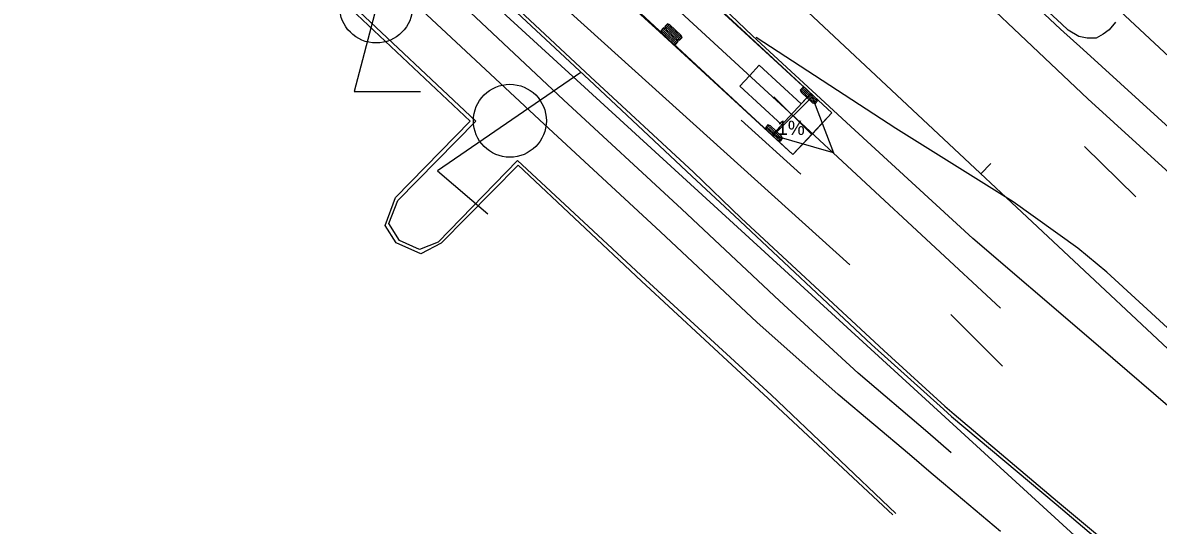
# Model space of a CAD drawing. Extents: x 1475900 to 1484331, y 375914 to 383395.
# Drawn here: x 1479629.9 to 1479789.2, y 379755.2 to 379825.7 of the extents above; entities that cross this region are included whole.
import ezdxf

# ---------------------------------------------------------------- set-up
doc = ezdxf.new("R2010")
doc.units = 0
for name, color, linetype in [('LT_X_Poles', 7, 'Continuous'), ('PM_X_CL_Double_Solid', 7, 'Continuous'), ('PM_X_Lane_Line', 7, 'Continuous'), ('PM_X_Misc', 7, 'Continuous'), ('PV_X_Curb', 7, 'Continuous'), ('PV_X_Walk', 7, 'Continuous'), ('RW_X_CL_20', 7, 'Continuous'), ('RW_X_Esmt_SH', 7, 'Continuous'), ('RW_X_Text', 7, 'Continuous')]:
    doc.layers.add(name, color=color, linetype=linetype)

# ---------------------------------------------------------------- blocks, each defined once
blk = doc.blocks.new('LPOLE')
at = {"layer": 'LT_X_Poles'}
blk.add_lwpolyline([(0.00999, 0.03751), (-0.01001, -0.0385), (0.02, -0.0385)], dxfattribs=at)
blk.add_circle((0, 0), 0.01651, dxfattribs=at)

msp = doc.modelspace()

# ---------------------------------------------------------------- linework, layer by layer
at = {"layer": 'PM_X_CL_Double_Solid'}
for points in [[(1479794.22, 379768.77), (1479779.09, 379781.77), (1479763.16, 379795.43), (1479746.62, 379810.62), (1479732.24, 379823.87), (1479714.72, 379840.65), (1479700.71, 379853.61), (1479677.93, 379875.07)], [(1479803.53, 379770.9), (1479781.95, 379790.71), (1479777.89, 379794.07), (1479768.81, 379800.57), (1479752.35, 379810.89), (1479732.76, 379823.63)]]:
    msp.add_lwpolyline(points, dxfattribs=at)
at = {"layer": 'PM_X_Lane_Line'}
for p, q in [((1479739.04, 379804.47), (1479730.66, 379812.05)), ((1479786.01, 379801.28), (1479778.82, 379808.36)), ((1479767.32, 379777.53), (1479760.1, 379784.77))]:
    msp.add_line(p, q, dxfattribs=at)
at = {"layer": 'PM_X_Misc'}
for p, q in [((1479735.27, 379810), (1479740.61, 379815.33)), ((1479740.61, 379810), (1479735.27, 379815.33)), ((1479767.04, 379785.65), (1479737.72, 379812.86))]:
    msp.add_line(p, q, dxfattribs=at)
for points in [[(1479725.98, 379829.12), (1479740.44, 379815.79), (1479735, 379809.93), (1479685.31, 379855.76)], [(1479724.38, 379830.7), (1479743.38, 379813.07), (1479737.93, 379807.21), (1479719.19, 379824.44), (1479707.65, 379835)], [(1479721.78, 379823.02), (1479719.72, 379824.93), (1479719.59, 379824.78), (1479721.64, 379822.88), (1479721.5, 379822.73), (1479719.45, 379824.63), (1479719.41, 379824.59), (1479719.57, 379824.25), (1479721.11, 379822.82), (1479721.46, 379822.68), (1479721.82, 379823.07), (1479721.66, 379823.41), (1479720.12, 379824.84), (1479719.77, 379824.98), (1479719.41, 379824.59)], [(1479722.32, 379823.61), (1479720.27, 379825.51), (1479720.13, 379825.37), (1479722.18, 379823.46), (1479722.05, 379823.32), (1479720, 379825.22), (1479719.95, 379825.17), (1479720.12, 379824.84), (1479721.66, 379823.41), (1479722, 379823.27), (1479722.37, 379823.66), (1479722.2, 379823.99), (1479720.66, 379825.42), (1479720.31, 379825.56), (1479719.95, 379825.17)], [(1479741.34, 379814.7), (1479739.28, 379816.6), (1479739.14, 379816.45), (1479741.2, 379814.55), (1479741.07, 379814.4), (1479739.01, 379816.3), (1479738.96, 379816.25), (1479739.13, 379815.92), (1479740.67, 379814.49), (1479741.02, 379814.36), (1479741.38, 379814.75), (1479741.21, 379815.08), (1479739.67, 379816.51), (1479739.32, 379816.64), (1479738.96, 379816.25)], [(1479736.44, 379809.42), (1479734.38, 379811.32), (1479734.24, 379811.17), (1479736.3, 379809.27), (1479736.17, 379809.13), (1479734.11, 379811.02), (1479734.06, 379810.98), (1479734.23, 379810.64), (1479735.77, 379809.22), (1479736.12, 379809.08), (1479736.48, 379809.47), (1479736.32, 379809.81), (1479734.77, 379811.23), (1479734.42, 379811.37), (1479734.06, 379810.98)]]:
    msp.add_lwpolyline(points, dxfattribs=at)
for points in [[(1479737.93, 379807.21), (1479715.94, 379827.62), (1479718.67, 379830.55), (1479721.39, 379833.48), (1479743.38, 379813.07), (1479740.65, 379810.14)], [(1479731.84, 379818.28), (1479733.2, 379819.75), (1479739.08, 379814.33), (1479740.43, 379815.8), (1479743.6, 379807.44), (1479735.01, 379809.92), (1479736.37, 379811.39), (1479730.48, 379816.81)]]:
    msp.add_lwpolyline(points, close=True, dxfattribs=at)
at = {"layer": 'PV_X_Curb'}
for points in [[(1479752.34, 379756.82), (1479734.89, 379773.49), (1479717.23, 379789.66), (1479699.3, 379806.4), (1479688.16, 379794.93), (1479685.53, 379793.9), (1479682.73, 379795.16), (1479681.26, 379797.55), (1479682.49, 379800.75), (1479693.46, 379811.91), (1479675.55, 379828.75), (1479655.83, 379847.06), (1479640.19, 379861.81), (1479628.56, 379849)], [(1479751.93, 379756.63), (1479734.45, 379772.98), (1479716.7, 379789.46), (1479699.4, 379805.74), (1479688.56, 379794.79), (1479685.72, 379793.29), (1479682.29, 379794.8), (1479680.73, 379797.25), (1479682.17, 379801.19), (1479692.65, 379811.91), (1479675.18, 379828.39), (1479655.51, 379846.68), (1479640.15, 379860.93), (1479629.13, 379848.87)], [(1479791.74, 379810.03), (1479778.64, 379821.98), (1479775.46, 379824.82), (1479758.38, 379840.84)], [(1479783.19, 379825.8), (1479782.3, 379824.72), (1479781.46, 379824.1), (1479780.47, 379823.55), (1479779.2, 379823.56), (1479778.04, 379823.77), (1479776.54, 379824.68), (1479775.61, 379825.57), (1479758.65, 379841.24)], [(1479695.13, 379830.98), (1479709.33, 379817.71), (1479723.73, 379804.19), (1479729.72, 379798.6), (1479748.96, 379780.55), (1479759.06, 379771.48), (1479760.18, 379770.47), (1479774.84, 379758.13), (1479787.83, 379747.16)], [(1479695.38, 379831.42), (1479709.51, 379818.13), (1479724, 379804.73), (1479730.66, 379798.27), (1479750.68, 379779.69), (1479759.25, 379771.89), (1479760.55, 379770.78), (1479775.03, 379758.53), (1479788.18, 379747.59)]]:
    msp.add_lwpolyline(points, dxfattribs=at)
at = {"layer": 'PV_X_Walk'}
for points in [[(1479767.05, 379754.29), (1479759.06, 379761.03), (1479757.31, 379762.48), (1479754.26, 379765.1), (1479744.26, 379773.56), (1479732.86, 379783.69), (1479719.35, 379796.38), (1479703.03, 379811.46), (1479682.44, 379830.69), (1479657.3, 379854.47), (1479652, 379859.64), (1479649.77, 379861.74), (1479651.8, 379859.82), (1479649.83, 379861.57), (1479642.24, 379868.78), (1479639.04, 379871.89), (1479636.88, 379872.56), (1479634.38, 379872.97), (1479631.75, 379873.28), (1479630.08, 379873.21), (1479625.85, 379872.76)], [(1479760.14, 379765.37), (1479756.86, 379768.22), (1479747.1, 379776.51), (1479736.05, 379786.7), (1479722.32, 379799.57), (1479705.73, 379814.89), (1479685.77, 379833.71)]]:
    msp.add_lwpolyline(points, dxfattribs=at)
at = {"layer": 'RW_X_CL_20'}
msp.add_line((1479764.31, 379804.52), (1479765.68, 379805.98), dxfattribs=at)
msp.add_lwpolyline([(1477185.15, 382318.79), (1478151.68, 381373.49), (1479566.7, 379989.54), (1480555.97, 379063.33), (1481343.87, 378335.5), (1481853.32, 377853.22), (1482587.9, 377143.51), (1482849.67, 376882.07), (1483668.91, 376080.34), (1483878.1, 376026.7), (1484025.82, 375988.83), (1484313.71, 375915.02)], dxfattribs=at)
at = {"layer": 'RW_X_Esmt_SH'}
msp.add_line((1479687.35, 379917.68), (1479967.32, 379655.56), dxfattribs=at)
msp.add_lwpolyline([(1479610.78, 379906.29), (1479798.35, 379734.62), (1479796.8, 379733.01), (1479926.31, 379611.76)], dxfattribs=at)
at = {"layer": 'RW_X_Text'}
for points in [[(1479792.31, 379997.56), (1479688.12, 379945.87), (1479680.71, 379942), (1479661.48, 379931.68), (1479658.87, 379928.92), (1479653.52, 379923.03), (1479651.72, 379914.38), (1479652.44, 379904.37), (1479656.24, 379892.75), (1479663.84, 379880.53), (1479675, 379870.68), (1479716.91, 379832.05), (1479737.94, 379812.66)], [(1479797.55, 379798.42), (1479779.29, 379815.04), (1479755.95, 379837.17), (1479710.6, 379878.47), (1479700.46, 379887.97), (1479695.14, 379892.26), (1479687.63, 379898.54), (1479684.65, 379909.71), (1479684.09, 379918.26), (1479685.98, 379925.49), (1479693.36, 379933.84), (1479703.54, 379940.07), (1479719.59, 379947.28), (1479755.69, 379965.71), (1479770.46, 379973.23)], [(1479448.85, 379819.27), (1479488.56, 379843.18), (1479509.21, 379852.71), (1479530.16, 379858.34), (1479557.4, 379865.65), (1479587.55, 379875.68), (1479607.72, 379882.39), (1479617.76, 379885.73), (1479628.56, 379887.41), (1479642.96, 379886.97), (1479656.29, 379879.24), (1479668.08, 379866.7), (1479698.14, 379834.91), (1479745.89, 379791.74)]]:
    msp.add_lwpolyline(points, dxfattribs=at)

# ---------------------------------------------------------------- block references
at = {"layer": 'LT_X_Poles', "xscale": 310.00000000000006, "yscale": 310.00000000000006}
msp.add_blockref('LPOLE', (1479679.46, 379827.99), dxfattribs=at)
at = {"layer": 'LT_X_Poles', "xscale": 310, "yscale": 310, "rotation": -40.78002837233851}
msp.add_blockref('LPOLE', (1479698.22, 379811.96), dxfattribs=at)

# ---------------------------------------------------------------- texts
at = {"layer": 'PM_X_Misc'}
msp.add_text('1%', height=2, dxfattribs=at).set_placement((1479735.72, 379809.96))

doc.saveas('drawing.dxf')
